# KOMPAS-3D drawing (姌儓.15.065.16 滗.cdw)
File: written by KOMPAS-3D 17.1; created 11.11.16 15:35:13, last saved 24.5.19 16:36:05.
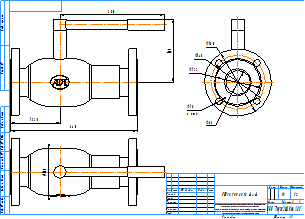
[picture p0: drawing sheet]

Sheet 1: A3, landscape

Title block, sheet 1: name: КШГИ.15.065.16 ф/ф; mass: 15; sheets: 1; organisation: ООО "Торговый дом АДЛ"; sheet format: A3; stored path: C:\Users\kka\KOMPAS_Work\КШП.ГИ\Ду50\КШГИ.15.50.16 ГЧ _ Кран шаровой газовый изолирующий  БИВАЛ Ду50 Ру16  полнопроходной фланцевый Габаритный чертеж.cdw

Views: Вид 1, Проекционный вид 2, Проекционный вид 3
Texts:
  Klimkovich
  ADL
  Рама для чертежей
  Лит-Масса-Масштаб
  Материал-Предприятие
  Масштаб
  Изм.
  Лист
  № докум.
  Подп.
  Дата
  Лит.
  Разраб.
  Пров.
  Т.контр.
  Листов
  Внимание! Данный продукт является объектом авторского права ООО «Торговый Дом АДЛ».
  Запрещается изменение, копирование, распространение
  (в том числе путем копирования на другие сайты и ресурсы в Интернете)
  или любое иное использование информации и объектов без предварительного
  согласия правообладателя (ООО «Торговый Дом АДЛ»).
  Н.контр.
  Утв.
  Изменение
  Номер документа
  Подпись
  Обозначение документа
  Наименование изделия
  Масса изделия по ГОСТ 2.109-73
  Порядковый номер листа
  Общее количество листов в документе
  Характер работы, выполненной лицом, подписавшим документ
  Наименование или индекс предприятия, выпускающего документ
  Инв. № подл.
  Подп. и дата
  Взам. инв. №
  Инв. № дубл.
  Инвентарный номер подлинника по ГОСТ 2.501-68
  Подпись принявшего подлинник в отдел технической документации
  Инвентарный номер подлинника, взамен которого выпущен данный подлинник
  Инвентарный номер дубликата по ГОСТ 2.502-68
  Подпись принявшего дубликат в отдел технической документации
  Справ. №
  Перв. примен.
  Обозначение документа, взамен или на основании которого выпущен данный документ
  Обозначение документа, в котором впервые записан данный документ
  Подпись лица, копировавшего чертеж
  Обозначение формата листа
  !Рама для чертежа
Dimensions and other numbers on the sheet: 280; 340; 132,5; 169; 180; 145; 122; 63; 18; 4 отв.; 127; 1:2; 1; 15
